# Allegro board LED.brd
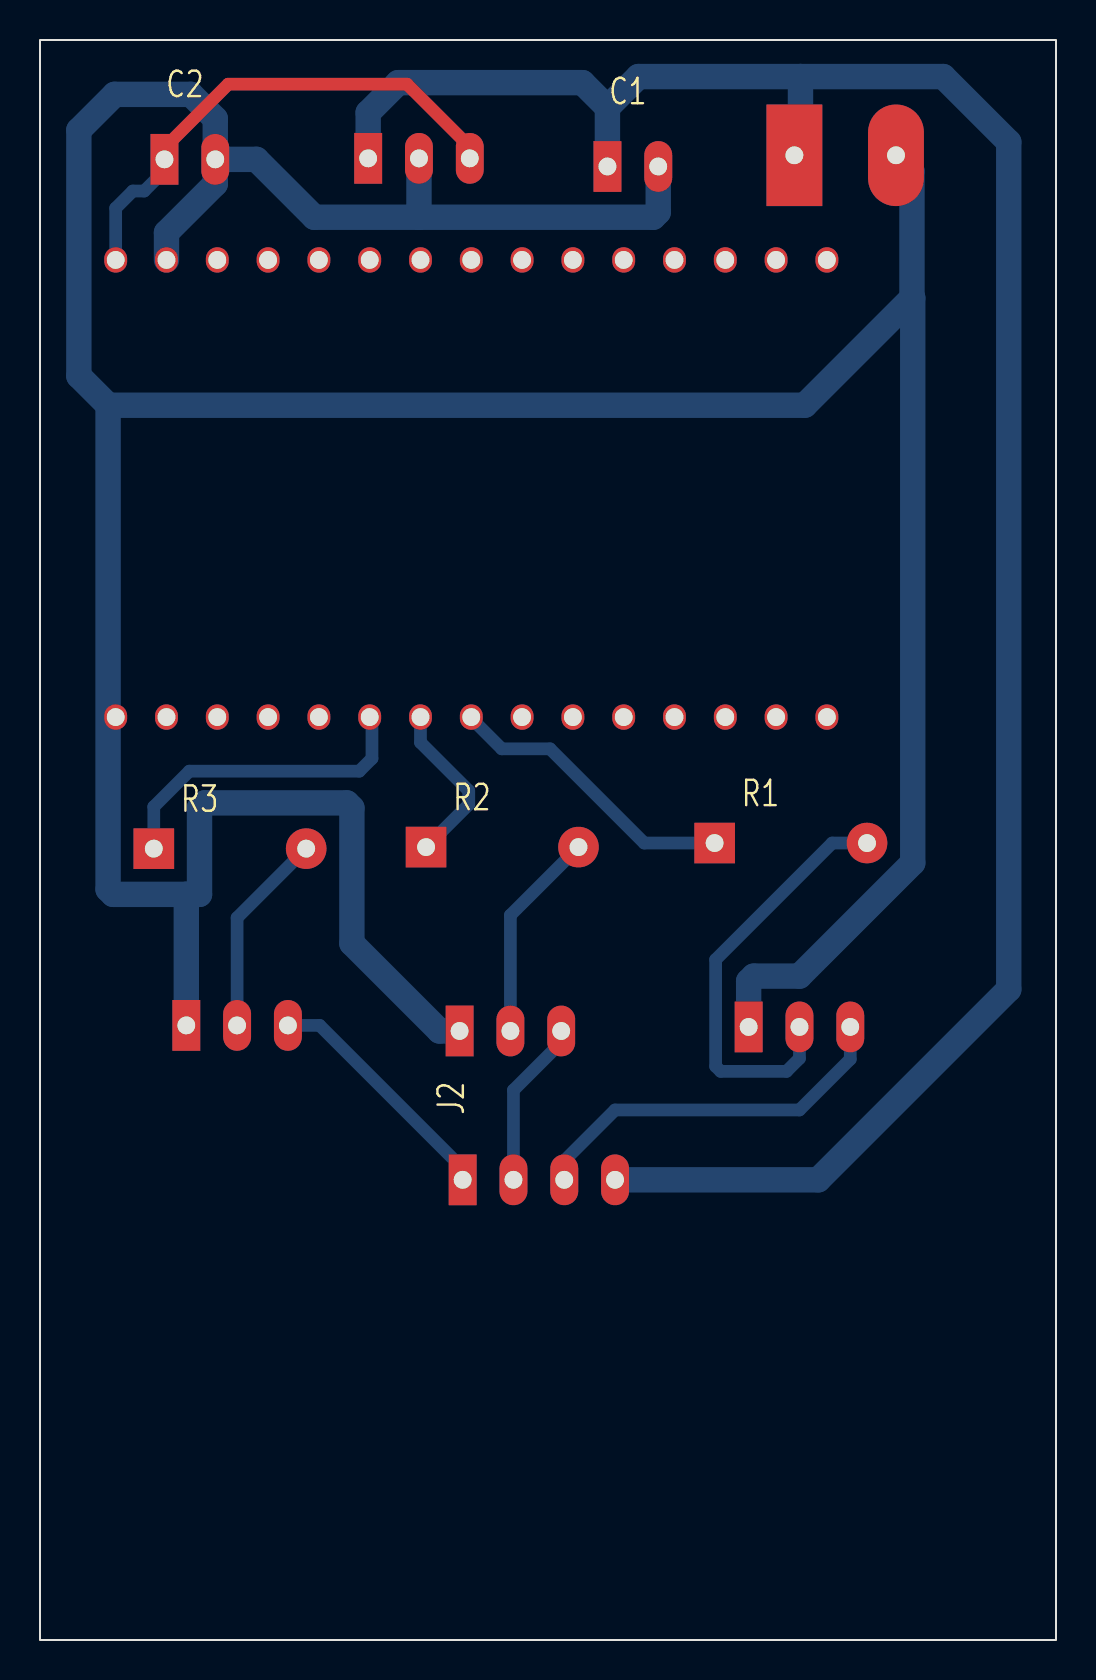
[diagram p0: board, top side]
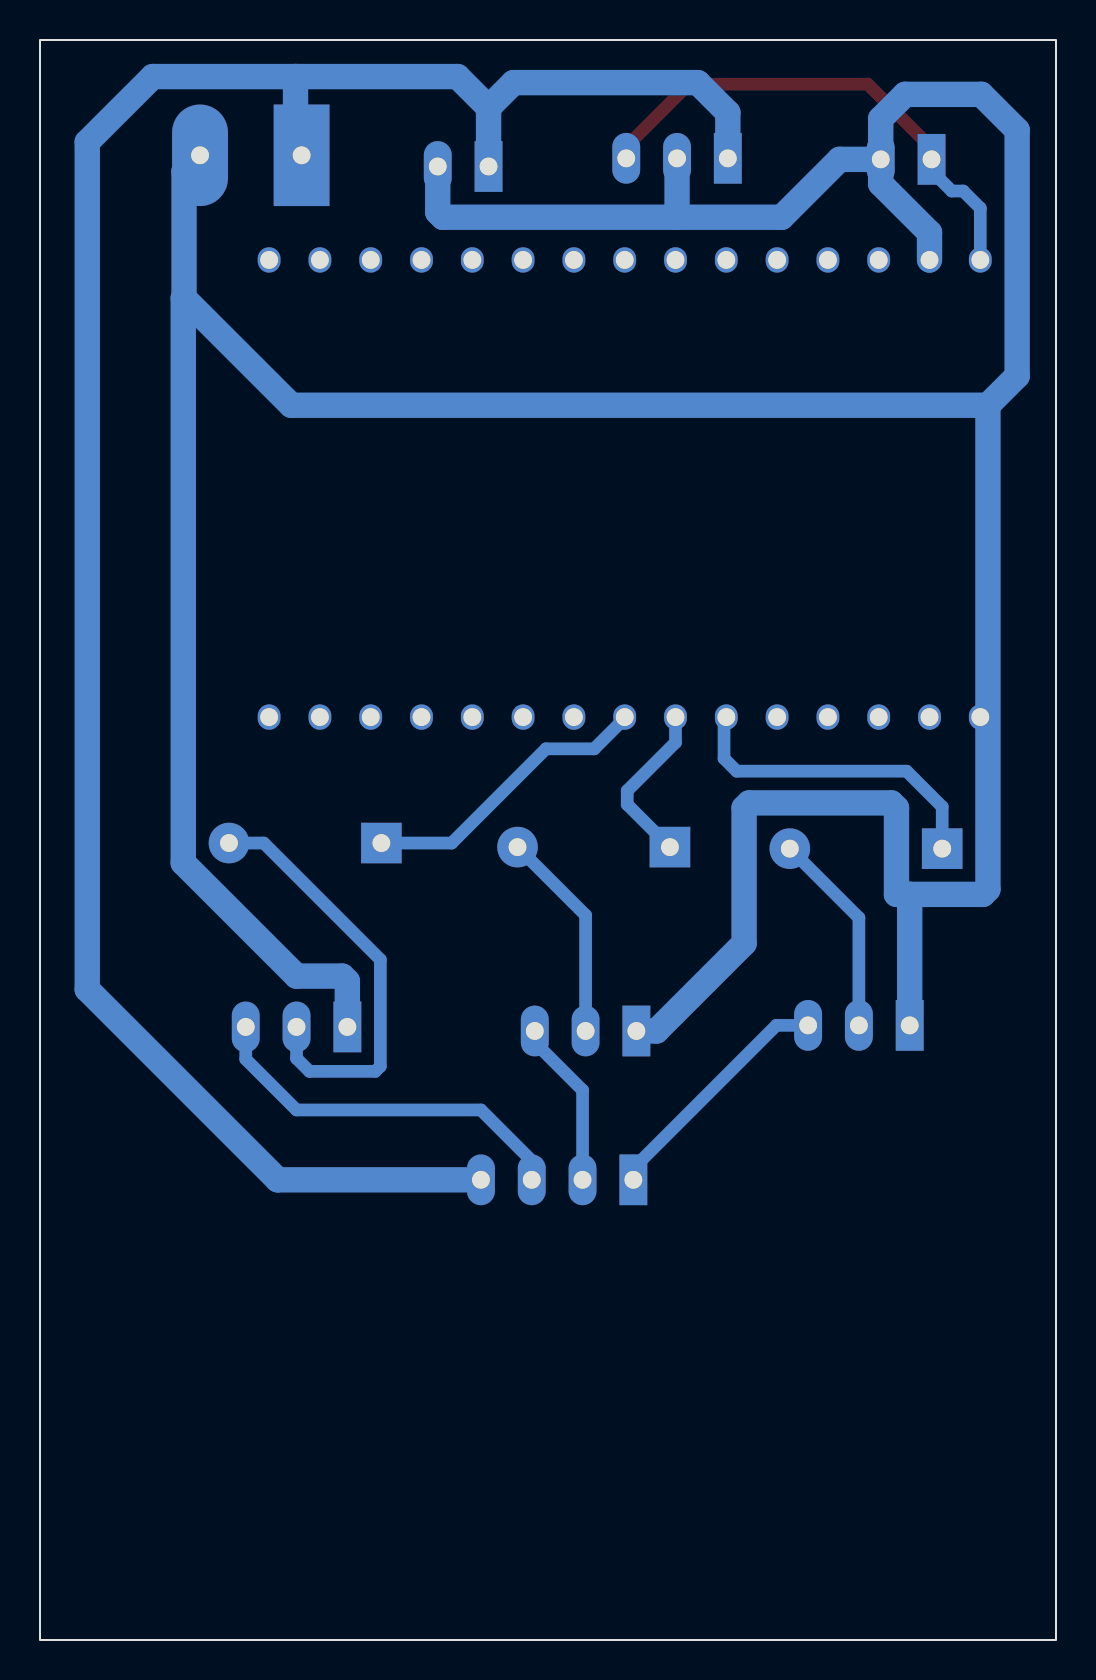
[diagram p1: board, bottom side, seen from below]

Outline 50.8 x 80.01 mm; copper layers: TOP, BOTTOM. Coordinates in mm from the lower left corner of the outline.
Outline path: rectangle 0,0 50.8,80.01

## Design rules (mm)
constraint set DEFAULT: min track width 0.635
nets with their own width: min track width 1.27; nets 12V GND

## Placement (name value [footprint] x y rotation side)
C1  0.33uf  [GU-CAPCYL100]  28.37 73.69 0 top
C2  0.33uf  [GU-CAPCYL100]  6.22 74.04 0 top
J1  HEADER 2  [GU-TERMINAL2-200]  37.72 74.24 90 top
J2  HEADER 4  [GU-MOLEX4]  21.13 23.01 90 top
Q1  2N2222  [GU-TO92-100]  35.43 30.66 0 top
Q2  2N2222  [GU-TO92-100]  20.98 30.45 0 top
Q3  2N2222  [GU-TO92-100]  7.32 30.73 0 top
R1  1K  [GU-RC300]  33.73 39.85 0 top
R2  1K  [GU-RC300]  19.3 39.65 0 top
R3  1K  [GU-RC300]  5.69 39.57 0 top
U2  ESP8266NodeMCU  [NODE]  21.56 57.58 90 top
U4  LM7805C/TO220  [GU-TO220AB]  16.41 74.09 0 top

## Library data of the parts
C1 C2 = CAPACITOR NON-POL
J1 = HEADER 2: User Part Number: TERMINAL2-200
J2 = HEADER 4
Q1-Q3 = 2N2222
R1-R3 = R
U2 = ESP8266NodeMCU_5
U4 = LM7805C/TO220_0

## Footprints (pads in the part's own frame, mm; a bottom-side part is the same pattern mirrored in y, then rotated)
GU-CAPCYL100
  rect 1.397x2.54 hole 0.889: 1(0,0)
  oval 1.397x2.54 hole 0.889: 2(2.54,0)
GU-MOLEX4
  rect 2.54x1.397 hole 0.889: 1(0,0)
  oval 2.54x1.397 hole 0.889: 2(0,-2.54) 3(0,-5.08) 4(0,-7.62)
GU-RC300
  rect 2.032x2.032 hole 0.889: 1(0,0)
  round 2.032 hole 0.889: 2(7.62,0)
GU-TERMINAL2-200
  rect 5.08x2.794 hole 0.889: 1(0,0)
  oval 5.08x2.794 hole 0.889: 2(0,-5.08)
GU-TO92-100
  rect 1.397x2.54 hole 0.889: 1(0,0)
  oval 1.397x2.54 hole 0.889: 2(2.54,0) 3(5.08,0)
GU-TO220AB
  rect 1.397x2.54 hole 0.889: 1(0,0)
  oval 1.397x2.54 hole 0.889: 2(2.54,0) 3(5.08,0)
NODE
  oval 1.27x1.143 hole 0.889: 1(-11.43,17.78) 2(-11.43,15.24) 3(-11.43,12.7) 4(-11.43,10.16) 5(-11.43,7.62) 6(-11.43,5.08) 7(-11.43,2.54) 8(-11.43,0) 9(-11.43,-2.54) 10(-11.43,-5.08) 11(-11.43,-7.62) 12(-11.43,-10.16) 13(-11.43,-12.7) 14(-11.43,-15.24) 15(-11.43,-17.78) 16(11.43,-17.78) 17(11.43,-15.24) 18(11.43,-12.7) 19(11.43,-10.16) 20(11.43,-7.62) 21(11.43,-5.08) 22(11.43,-2.54) 23(11.43,0) 24(11.43,2.54) 25(11.43,5.08) 26(11.43,7.62) 27(11.43,10.16) 28(11.43,12.7) 29(11.43,15.24) 30(11.43,17.78)

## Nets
12V: C1.1 J1.1 J2.4 U4.1
GND: C1.2 C2.2 J1.2 Q1.1(EMITTER) Q2.1(EMITTER) Q3.1(EMITTER) U2.29 U4.2
N26259: Q2.2 R2.2
N26267: Q3.2 R3.2
N28423: C2.1 U2.30 U4.3(OUT)
N28430: R1.1 U2.8
N28437: R2.1 U2.7
N28467: R3.1 U2.6
N28563: J2.3 Q1.3
N28577: J2.1 Q3.3
N29703: J2.2 Q2.3
N33667: Q1.2 R1.2

Pads without a net: U2 1 2 3 4 5 9 10 11 12 13 14 15 16 17 18 19 20 21 22 23 24 25 26 27 28

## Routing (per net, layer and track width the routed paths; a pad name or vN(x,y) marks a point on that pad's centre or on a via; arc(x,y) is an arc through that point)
12V: length 110.5
  BOTTOM w1.27: 28.37,76.63 29.92,78.18 38.02,78.18 ; 28.37,76.63 C1.1 ; 28.37,76.63 27.13,77.88 17.91,77.88 16.41,76.38 U4.1 ; J2.4 38.91,23.01 48.44,32.54 48.44,74.9 45.16,78.18 38.02,78.18 ; 38.02,78.18 38.02,74.55 J1.1
GND: length 211.8
  BOTTOM w1.27: C2.2 8.76,72.82 6.32,70.38 U2.29 ; C2.2 10.82,74.04 13.72,71.15 18.95,71.15 ; C2.2 8.76,76.07 7.54,77.29 3.73,77.29 1.94,75.5 1.94,63.21 3.4,61.75 ; 43.6,67.11 38.24,61.75 3.4,61.75 ; 43.6,67.11 43.64,67.11 43.64,38.86 37.97,33.2 35.69,33.2 35.43,32.94 Q1.1 ; 43.6,67.11 43.6,73.44 J1.2 ; 3.4,61.75 3.4,37.54 3.66,37.29 7.32,37.29 ; 7.32,37.29 7.98,37.29 7.98,41.61 8.23,41.86 15.34,41.86 15.6,41.61 15.6,34.84 19.98,30.45 Q2.1 ; 7.32,37.29 Q3.1 ; 18.95,71.15 U4.2 ; 18.95,71.15 30.66,71.15 30.91,71.4 C1.2
N26259: length 10.6
  BOTTOM w0.635: Q2.2 23.52,36.25 R2.2
N26267: length 10.3
  BOTTOM w0.635: R3.2 9.86,36.12 Q3.2
N28423: length 25.4
  TOP w0.635: C2.1 6.22,74.61 9.41,77.8 18.35,77.8 21.49,74.66 U4.3
  BOTTOM w0.635: U2.30 3.78,71.6 4.64,72.46 5.21,72.46 6.22,73.47 C2.1
N28430: length 14.8
  BOTTOM w0.635: U2.8 21.56,46.09 23.09,44.56 25.5,44.56 30.21,39.85 R1.1
N28437: length 8.4
  BOTTOM w0.635: R2.1 21.44,41.78 21.44,42.47 19.02,44.88 U2.7
N28467: length 16.1
  BOTTOM w0.635: R3.1 5.69,41.67 7.47,43.45 15.96,43.45 16.6,44.08 16.6,46.04 U2.6
N28563: length 19
  BOTTOM w0.635: J2.3 26.21,23.96 28.75,26.5 37.97,26.5 40.51,29.04 Q1.3
N28577: length 12.3
  BOTTOM w0.635: J2.1 21.13,23.58 13.98,30.73 Q3.3
N29703: length 8.4
  BOTTOM w0.635: J2.2 23.67,27.5 26.06,29.88 Q2.3
N33667: length 21.5
  BOTTOM w0.635: Q1.2 37.97,29.08 37.33,28.44 34.04,28.44 33.78,28.69 33.78,34.02 39.61,39.85 R1.2
